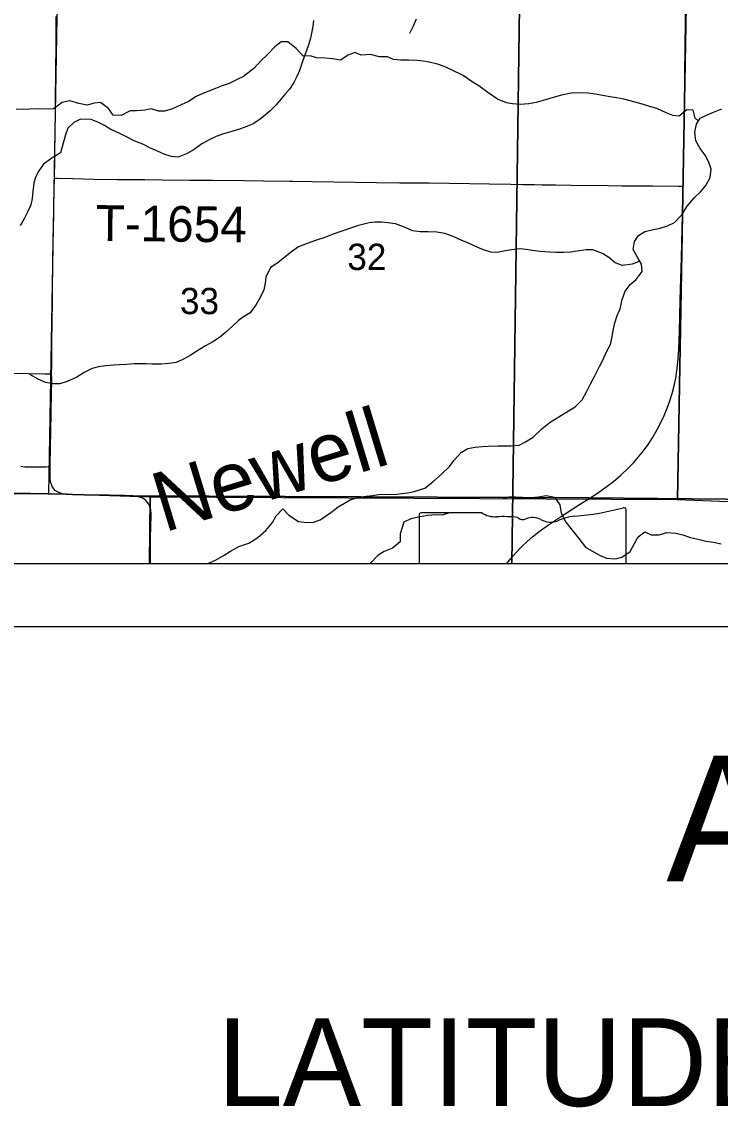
# Model space of a CAD drawing. Extents: x 0 to 34, y 0 to 22.
# Drawn here: x 14.009 to 15.122, y 13.234 to 14.964 of the extents above; entities that cross this region are included whole.
import ezdxf

# ---------------------------------------------------------------- set-up
doc = ezdxf.new("R2010")
doc.units = 0
for name, color, linetype in [('Default', 7, 'Continuous'), ('GM_X_Corporation_Text', 7, 'Continuous'), ('GM_X_County_Road', 7, 'Continuous'), ('GM_X_Minor_River', 7, 'Continuous'), ('GM_X_Minor_River_Text', 7, 'Continuous'), ('GM_X_Rail_Line', 7, 'Continuous'), ('GM_X_Section', 7, 'Continuous'), ('GM_X_Section_Text', 7, 'Continuous'), ('GM_X_State_Route', 7, 'Continuous'), ('GM_X_Township_Road', 7, 'Continuous'), ('GM_X_Township_Road_Text', 7, 'Continuous'), ('GM_X_US_Shield', 7, 'Continuous'), ('SH_Data', 7, 'Continuous'), ('SH_Text', 7, 'Continuous')]:
    doc.layers.add(name, color=color, linetype=linetype)

msp = doc.modelspace()

# ---------------------------------------------------------------- linework, layer by layer
at = {"layer": 'Default'}
for points in [[(13.7837, 14.1), (14.7899, 14.1), (14.8027, 15.0271), (13.8003, 15.0417)], [(14.7899, 14.1), (15.803, 14.1), (15.8146, 15.0251), (14.8027, 15.0271)]]:
    msp.add_lwpolyline(points, close=True, dxfattribs=at)
at = {"layer": 'GM_X_Corporation_Text'}
msp.add_line((14.7419, 14.1809), (14.6453, 14.1809), dxfattribs=at)
msp.add_lwpolyline([(14.6421, 14.1774), (14.6421, 14.1), (14.9717, 14.1), (14.9717, 14.186)], dxfattribs=at)
for centre, major_axis, start_param, end_param in [((14.8543, 14.4537), (0.3495, 0), 4.814394, 5.042369), ((14.9681, 14.1863), (0.00367, 0), 6.197627, 7.989034), ((14.6459, 14.1779), (0.00382, 0), 1.727492, 3.291633), ((14.7649, 14.2041), (0.037, 0), 4.042888, 4.731792), ((14.7772, 14.0685), (0.133, 0), 1.404758, 1.657859), ((14.8074, 14.1789), (0.0107, 0), 3.836095, 5.185415), ((14.823, 14.1558), (0.0222, 0), 0.950623, 2.079405), ((14.8517, 14.1875), (0.0267, 0), 4.08156, 5.145723), ((14.8989, 14.1198), (0.0703, 0), 1.699012, 2.107814)]:
    msp.add_ellipse(centre, major_axis=major_axis, ratio=0.8, start_param=start_param, end_param=end_param, dxfattribs=at)
at = {"layer": 'GM_X_County_Road'}
for points in [[(14.061, 14.7145), (14.061, 14.7184), (14.0615, 14.7393), (14.0617, 14.7579), (14.062, 14.7827), (14.0623, 14.7983), (14.0626, 14.8107), (14.0627, 14.823), (14.0629, 14.8478), (14.0631, 14.8726), (14.0634, 14.8913), (14.0639, 14.9192), (14.0639, 14.944), (14.0638, 14.972)], [(14.0566, 14.4026), (14.0567, 14.4162), (14.0567, 14.4362), (14.0568, 14.4506), (14.0574, 14.4859), (14.0578, 14.5168), (14.0581, 14.5343), (14.0586, 14.579), (14.0591, 14.6182), (14.0599, 14.6543), (14.0602, 14.6702), (14.0608, 14.6964), (14.061, 14.7145)], [(14.0543, 14.2546), (14.0544, 14.2621), (14.0547, 14.2801), (14.055, 14.2925), (14.0552, 14.304), (14.0554, 14.3165), (14.0557, 14.3346), (14.0559, 14.3474), (14.0562, 14.3677), (14.0567, 14.3946), (14.0566, 14.4026)], [(14.0805, 14.2102), (14.0732, 14.2113), (14.0668, 14.2139), (14.0624, 14.2166), (14.0595, 14.2196), (14.0574, 14.2229), (14.0562, 14.2261), (14.0548, 14.2305), (14.0543, 14.2376), (14.0542, 14.2456), (14.0543, 14.2546)], [(14.2141, 14.1), (14.2141, 14.1061), (14.2143, 14.1218), (14.2143, 14.1371), (14.2148, 14.1638), (14.2149, 14.1719), (14.2149, 14.1793), (14.2145, 14.1857), (14.2123, 14.1931), (14.2096, 14.1971), (14.2066, 14.2005), (14.2058, 14.2015), (14.2003, 14.2048), (14.1939, 14.2066), (14.1864, 14.2076), (14.1731, 14.208), (14.1489, 14.2084), (14.1085, 14.2091), (14.0899, 14.2098), (14.0817, 14.2102), (14.0805, 14.2102)]]:
    msp.add_lwpolyline(points, dxfattribs=at)
at = {"layer": 'GM_X_Minor_River'}
for points in [[(14.6371, 14.9675), (14.6325, 14.9568), (14.6267, 14.9451)], [(14.4736, 14.9657), (14.4728, 14.9562), (14.4705, 14.9456)], [(15.0871, 14.8053), (15.082, 14.8101), (15.0786, 14.8227), (15.0687, 14.8231), (15.0561, 14.8129), (15.0463, 14.8141), (15.0357, 14.8183), (15.0205, 14.8252), (15.011, 14.8279), (14.9996, 14.8318), (14.9898, 14.8345), (14.9784, 14.8375), (14.9682, 14.8403), (14.9564, 14.8422), (14.9465, 14.8441), (14.9344, 14.8461), (14.923, 14.8481), (14.9116, 14.8496), (14.8964, 14.8505), (14.8843, 14.8497), (14.8691, 14.8468), (14.8554, 14.843), (14.8433, 14.8393), (14.8284, 14.8352), (14.817, 14.8329), (14.803, 14.8319), (14.7908, 14.8327), (14.7814, 14.8346), (14.7669, 14.8404), (14.7514, 14.8511), (14.7374, 14.8614), (14.7268, 14.8679), (14.712, 14.8779), (14.6938, 14.8871), (14.6821, 14.8924), (14.6711, 14.8959), (14.6582, 14.899), (14.6487, 14.9006), (14.6388, 14.9018), (14.6256, 14.9022), (14.613, 14.9026), (14.6013, 14.9034), (14.5918, 14.9077), (14.5789, 14.9077), (14.5645, 14.9112), (14.5497, 14.9105), (14.5394, 14.9147), (14.5288, 14.9102), (14.517, 14.9023), (14.5048, 14.9046), (14.4923, 14.9058), (14.4783, 14.9063), (14.4684, 14.9094), (14.4574, 14.909), (14.4464, 14.9209), (14.4328, 14.9316), (14.4222, 14.9316), (14.4123, 14.9237), (14.3997, 14.9108), (14.3898, 14.9013), (14.3787, 14.8892), (14.362, 14.8764), (14.3521, 14.8715), (14.3395, 14.8651), (14.3285, 14.8617), (14.3125, 14.8553), (14.2977, 14.8493), (14.2867, 14.8444), (14.2745, 14.8365), (14.2631, 14.8312), (14.249, 14.8249), (14.2365, 14.8211), (14.227, 14.8211), (14.2152, 14.8246), (14.2054, 14.8228), (14.1917, 14.8217), (14.1818, 14.8217), (14.1674, 14.8142), (14.1545, 14.815), (14.1473, 14.8253), (14.1344, 14.8349), (14.1242, 14.8341), (14.1131, 14.8308), (14.0999, 14.8335), (14.0858, 14.8377), (14.0733, 14.8351), (14.0596, 14.8249), (14.047, 14.8242), (14.0353, 14.825), (14.022, 14.8243), (14.0098, 14.824), (14.0003, 14.8244)], [(14.4705, 14.9456), (14.4682, 14.9353), (14.4655, 14.9255), (14.4563, 14.9004), (14.4514, 14.886), (14.4472, 14.8765), (14.4422, 14.867), (14.4353, 14.8564), (14.4277, 14.847), (14.4144, 14.8314), (14.4041, 14.8212), (14.3911, 14.8102), (14.3786, 14.8015), (14.3675, 14.7966), (14.3557, 14.7925), (14.3439, 14.7887), (14.3287, 14.7846), (14.3189, 14.7808), (14.3086, 14.7759), (14.296, 14.7691), (14.2835, 14.7601), (14.2717, 14.7529), (14.2584, 14.748), (14.2477, 14.7488), (14.2371, 14.7519), (14.225, 14.7572), (14.2143, 14.7622), (14.2018, 14.7683), (14.1893, 14.7733), (14.1756, 14.7802), (14.1639, 14.7859), (14.151, 14.7921), (14.1407, 14.7982), (14.1313, 14.8031), (14.1195, 14.8077), (14.1028, 14.8082), (14.0921, 14.8033), (14.0826, 14.7938), (14.0784, 14.7836), (14.0749, 14.7699), (14.0707, 14.7547), (14.057, 14.746), (14.0437, 14.7366), (14.0361, 14.726), (14.0307, 14.7157), (14.0284, 14.7062), (14.0268, 14.6929), (14.0257, 14.6819), (14.0234, 14.6717), (14.0184, 14.661), (14.0127, 14.6493), (14.0066, 14.6383)], [(14.6029, 14.2101), (14.6147, 14.2115), (14.6242, 14.213), (14.6341, 14.2149), (14.6512, 14.2205), (14.6637, 14.2303), (14.6778, 14.2424), (14.6904, 14.2549), (14.698, 14.2651), (14.7098, 14.2776), (14.7197, 14.2836), (14.7315, 14.2855), (14.7425, 14.2866), (14.752, 14.2873), (14.7676, 14.2876), (14.7782, 14.2879), (14.7881, 14.2875), (14.8014, 14.289), (14.8113, 14.2939), (14.8235, 14.3018), (14.8375, 14.315), (14.8509, 14.3256), (14.8646, 14.3339), (14.8802, 14.3437), (14.8904, 14.3501), (14.9019, 14.3611), (14.9095, 14.3747), (14.9149, 14.3865), (14.9221, 14.3994), (14.9294, 14.4141), (14.9348, 14.4244), (14.9413, 14.4384), (14.947, 14.4494), (14.9497, 14.4615), (14.9513, 14.4714), (14.9536, 14.4839), (14.9574, 14.4957), (14.9624, 14.5063), (14.9655, 14.5207), (14.9705, 14.5344), (14.9785, 14.545), (14.988, 14.5529), (14.9975, 14.5658), (14.9961, 14.5772), (14.9904, 14.5875), (14.9832, 14.6004), (14.9852, 14.6134), (14.9913, 14.6232), (15.0019, 14.6292), (15.0156, 14.6326), (15.0263, 14.6348), (15.0377, 14.6386), (15.0487, 14.6438), (15.0605, 14.656), (15.0693, 14.6696), (15.08, 14.6832), (15.0903, 14.6927), (15.0987, 14.7029), (15.1059, 14.7154), (15.1075, 14.7287), (15.103, 14.7409), (15.0977, 14.7508), (15.0897, 14.7614), (15.083, 14.774), (15.0811, 14.7877), (15.0842, 14.8002), (15.0899, 14.8101), (15.0998, 14.815), (15.1112, 14.8195), (15.1242, 14.8251)], [(14.9935, 14.5819), (14.9816, 14.5773), (14.9661, 14.5754), (14.9543, 14.5793), (14.9441, 14.5877), (14.9342, 14.5942), (14.9187, 14.6), (14.9081, 14.6), (14.894, 14.5982), (14.883, 14.5963), (14.872, 14.596), (14.8598, 14.5957), (14.85, 14.5965), (14.8348, 14.5977), (14.8226, 14.5989), (14.8124, 14.6008), (14.8029, 14.6016), (14.7892, 14.6002), (14.7794, 14.5983), (14.7664, 14.5957), (14.7562, 14.5965), (14.7463, 14.5996), (14.7365, 14.6034), (14.7209, 14.6107), (14.7092, 14.6157), (14.6963, 14.6215), (14.683, 14.6261), (14.6701, 14.6284), (14.6565, 14.6289), (14.6435, 14.6286), (14.6322, 14.6305), (14.617, 14.6367), (14.6045, 14.6413), (14.592, 14.6432), (14.5821, 14.644), (14.5722, 14.6441), (14.5624, 14.643), (14.5453, 14.6389), (14.5357, 14.6359), (14.519, 14.6299), (14.5053, 14.625), (14.4916, 14.6197), (14.4772, 14.6149), (14.4635, 14.6104), (14.4498, 14.6047), (14.4388, 14.5968), (14.4262, 14.5866), (14.4167, 14.5794), (14.4053, 14.5719), (14.398, 14.5567), (14.3968, 14.5472), (14.3949, 14.5366), (14.3892, 14.5252), (14.3823, 14.5131), (14.3731, 14.4998), (14.3606, 14.4923), (14.3541, 14.4874), (14.3446, 14.4783), (14.3335, 14.4685), (14.324, 14.4602), (14.3134, 14.4534), (14.3016, 14.4473), (14.2879, 14.4387), (14.2772, 14.4319), (14.2658, 14.4251), (14.2548, 14.4206), (14.2438, 14.4187), (14.2316, 14.418), (14.2168, 14.4181), (14.2073, 14.4185), (14.1978, 14.4182), (14.1879, 14.4182), (14.1762, 14.4175), (14.1648, 14.4168), (14.1553, 14.4165), (14.1428, 14.4154), (14.131, 14.4139), (14.1211, 14.4109), (14.1082, 14.4045), (14.0968, 14.3973), (14.0812, 14.3902), (14.0694, 14.3865), (14.0595, 14.3865), (14.047, 14.3888), (14.0349, 14.3942), (14.022, 14.4015)], [(14.3052, 14.1), (14.3174, 14.1057), (14.3315, 14.1136), (14.3418, 14.1201), (14.3547, 14.1272), (14.3707, 14.1328), (14.3851, 14.1419), (14.3977, 14.1529), (14.4087, 14.1653), (14.4141, 14.1763), (14.4248, 14.1873), (14.4346, 14.1774), (14.4501, 14.1674), (14.463, 14.1655), (14.474, 14.1662), (14.4843, 14.1696), (14.5014, 14.1813), (14.5132, 14.1903), (14.5231, 14.1964), (14.5334, 14.2024), (14.5463, 14.2061), (14.5577, 14.2076), (14.5676, 14.2087), (14.5771, 14.2102), (14.5904, 14.2105), (14.6029, 14.2101)], [(14.7759, 14.2039), (14.7862, 14.2062), (14.7957, 14.2065), (14.8067, 14.2061), (14.82, 14.2056), (14.8321, 14.2067), (14.8446, 14.2086), (14.8575, 14.2059), (14.8662, 14.1937), (14.8681, 14.1804), (14.876, 14.1659), (14.8858, 14.1533), (14.8964, 14.14), (14.907, 14.1262), (14.921, 14.1182), (14.9305, 14.1132), (14.9407, 14.1086), (14.9548, 14.1074), (14.965, 14.1104), (14.9783, 14.1195), (14.9852, 14.132), (14.991, 14.1426), (15.0016, 14.1505), (15.0115, 14.1459), (15.0244, 14.1458), (15.0369, 14.1496), (15.051, 14.1484), (15.062, 14.1457), (15.0745, 14.1418), (15.0889, 14.1383), (15.0991, 14.1356), (15.1109, 14.1341), (15.123, 14.1317)], [(14.6906, 14.1811), (14.679, 14.177), (14.6691, 14.1778), (14.6555, 14.1767), (14.6437, 14.1745), (14.6289, 14.1715), (14.6178, 14.1659), (14.6117, 14.1477), (14.6116, 14.1348), (14.5998, 14.1246), (14.5865, 14.1193), (14.5766, 14.1133), (14.5648, 14.1008), (14.5642, 14.1)]]:
    msp.add_lwpolyline(points, dxfattribs=at)
at = {"layer": 'GM_X_Rail_Line'}
msp.add_lwpolyline([(13.2404, 20.2494), (13.2404, 14.2201), (13.6735, 14.2183), (14.0803, 14.2108), (14.0815, 14.2107), (14.0897, 14.2103), (14.1083, 14.2096), (14.1487, 14.209), (14.1729, 14.2085), (14.1862, 14.2082), (14.913, 14.2046), (16.2742, 14.1914), (17.6045, 14.1785), (18.188, 14.1728), (18.7997, 14.167), (19.082, 14.1642), (19.0858, 15.176)], dxfattribs=at)
msp.add_lwpolyline([(13.2404, 14.2201), (13.2404, 14.1), (19.0825, 14.1), (19.082, 14.1642), (18.7997, 14.167), (18.188, 14.1728), (17.6045, 14.1785), (16.2742, 14.1914), (14.913, 14.2046), (14.1862, 14.2082), (14.1729, 14.2085), (14.1487, 14.209), (14.1083, 14.2096), (14.0897, 14.2103), (14.0815, 14.2107), (14.0803, 14.2108), (13.6735, 14.2183)], close=True, dxfattribs=at)
at = {"layer": 'GM_X_Section'}
for points in [[(15.0711, 15.2009), (15.0535, 14.2019), (14.2133, 14.2058), (14.0522, 14.2111), (14.0694, 15.2136)], [(16.0735, 15.1863), (16.0597, 14.1843), (15.2415, 14.1943), (15.0535, 14.2019), (15.0711, 15.2009)]]:
    msp.add_lwpolyline(points, close=True, dxfattribs=at)
at = {"layer": 'GM_X_State_Route'}
for points in [[(15.0625, 14.7015), (15.0625, 14.7029), (15.0632, 14.7464), (15.0643, 14.7992), (15.065, 14.8427), (15.0653, 14.8614), (15.0654, 14.88), (15.0663, 14.9638), (15.0665, 14.9855), (15.0667, 15.0072), (15.067, 15.0259), (15.0672, 15.0414), (15.0676, 15.0723), (15.0677, 15.0878), (15.0678, 15.1033), (15.0688, 15.1562), (15.0686, 15.1841), (15.069, 15.2033)], [(14.9132, 14.204), (14.9264, 14.2125), (14.9416, 14.2234), (14.9515, 14.231), (14.9634, 14.241), (14.9747, 14.2517), (14.9835, 14.2606), (14.9917, 14.27), (14.9995, 14.2797), (15.0068, 14.2899), (15.0136, 14.3003), (15.0215, 14.3137), (15.0274, 14.3247), (15.0327, 14.336), (15.0374, 14.3476), (15.0416, 14.3593), (15.0453, 14.3712), (15.0483, 14.3833), (15.0508, 14.3955), (15.0532, 14.4109), (15.0549, 14.4264), (15.056, 14.442), (15.0571, 14.4699), (15.0581, 14.5196), (15.06, 14.588), (15.0615, 14.6563), (15.0625, 14.7015)], [(14.7816, 14.1), (14.7883, 14.1084), (14.7965, 14.1177), (14.8051, 14.1266), (14.8141, 14.1351), (14.8234, 14.1432), (14.8356, 14.1528), (14.8482, 14.1618), (14.8688, 14.1756), (14.8976, 14.194), (14.9132, 14.204)]]:
    msp.add_lwpolyline(points, dxfattribs=at)
at = {"layer": 'GM_X_Township_Road'}
for points in [[(14.061, 14.7145), (14.0655, 14.7143), (14.0901, 14.7137), (14.1245, 14.713), (14.1617, 14.7124), (14.1833, 14.7122), (14.205, 14.712), (14.2329, 14.7117), (14.2764, 14.7112), (14.2852, 14.7112)], [(14.2852, 14.7112), (14.3136, 14.7112), (14.3633, 14.7107), (14.3943, 14.7102), (14.4359, 14.7094)], [(14.4359, 14.7094), (14.4408, 14.7093), (14.4718, 14.7089), (14.506, 14.7085), (14.5401, 14.7081), (14.5742, 14.7076), (14.6115, 14.7071), (14.658, 14.7067), (14.7542, 14.7051), (14.7884, 14.7047), (14.8069, 14.7043), (14.8256, 14.704), (14.838, 14.7039), (14.8595, 14.7037), (14.8845, 14.7033), (14.9433, 14.7025), (14.965, 14.7023), (15.0146, 14.7023), (15.0551, 14.7016), (15.0625, 14.7015)], [(13.972, 14.404), (14.0185, 14.4032), (14.0464, 14.4027), (14.0566, 14.4026)], [(14.0077, 14.2551), (14.0139, 14.2545), (14.0263, 14.2542), (14.048, 14.2545), (14.0543, 14.2546)]]:
    msp.add_lwpolyline(points, dxfattribs=at)
at = {"layer": 'GM_X_US_Shield'}
for points in [[(13.2404, 15.2209), (13.2404, 14.2178), (14.0522, 14.2111), (14.0694, 15.2136)], [(13.2404, 14.2178), (13.2404, 14.1), (14.2126, 14.1), (14.2133, 14.2058), (14.0522, 14.2111)], [(14.2126, 14.1), (15.2406, 14.1), (15.2415, 14.1943), (15.0535, 14.2019), (14.2133, 14.2058)]]:
    msp.add_lwpolyline(points, close=True, dxfattribs=at)
at = {"layer": 'SH_Data'}
for p, q in [((13.2404, 14.1), (20.0404, 14.1)), ((13.1404, 14), (20.1404, 14))]:
    msp.add_line(p, q, dxfattribs=at)

# ---------------------------------------------------------------- texts
at = {"layer": 'GM_X_Minor_River_Text'}
msp.add_text('Newell', height=0.09472, rotation=16.9079, dxfattribs=at).set_placement((14.2355, 14.1494))
at = {"layer": 'GM_X_Section_Text'}
for s, p in [('32', (14.5276, 14.568)), ('33', (14.261, 14.4976))]:
    msp.add_text(s, height=0.04186, rotation=0, dxfattribs=at).set_placement(p)
at = {"layer": 'GM_X_Township_Road_Text'}
msp.add_text('T-1654', height=0.05682, rotation=359.2964, dxfattribs=at).set_placement((14.1264, 14.6147))
at = {"layer": 'SH_Text'}
for s, height, p in [('ASD-250 LOCATION MAP', 0.2, (15.0359, 13.5938)), ('LATITUDE:  40°51\'26" N    LONGITUDE:  82°14\'00" W', 0.14, (14.3207, 13.2355))]:
    msp.add_text(s, height=height, dxfattribs=at).set_placement(p)

doc.saveas('drawing.dxf')
